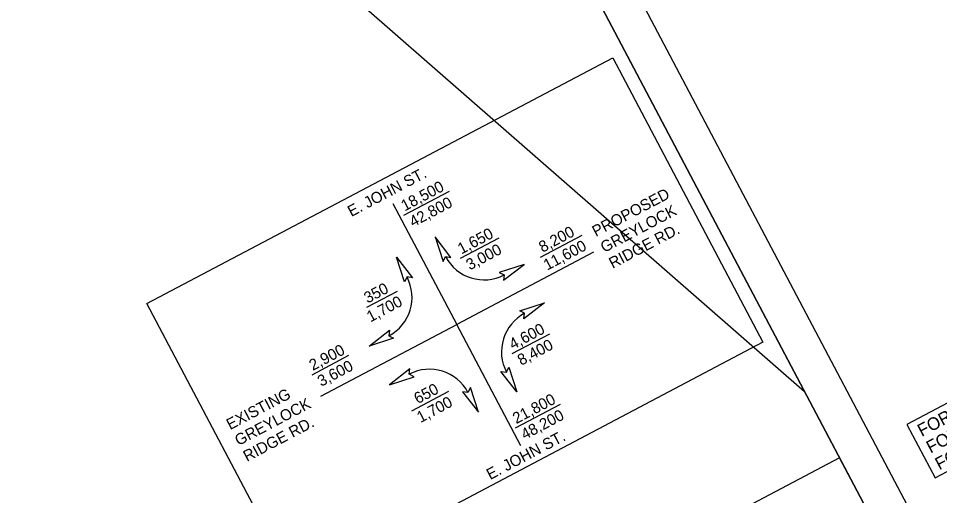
# Model space of a CAD drawing. Extents: x 1486990 to 1489232, y 497582 to 499336.
# Drawn here: x 1488614.3 to 1489025.8, y 498447.2 to 498660.3 of the extents above; entities that cross this region are included whole.
import ezdxf

# ---------------------------------------------------------------- set-up
doc = ezdxf.new("R2010")
doc.units = 0
for name, color, linetype in [('PROF-AXIS', 7, 'Continuous'), ('Prop Drainage Ditch Boundaries', 7, 'Continuous'), ('Prop Drainage Structure Catch Basin Open Throat 1 CELL', 7, 'Continuous'), ('Prop Drainage Structure Pipe Alternate 15in', 7, 'Continuous'), ('Prop Drainage Structure Plot Symbol 20 Scale', 7, 'Continuous'), ('Prop Earthen Structure V Ditch Berm Detail CELL', 7, 'Continuous')]:
    doc.layers.add(name, color=color, linetype=linetype)

msp = doc.modelspace()

# ---------------------------------------------------------------- linework, layer by layer
at = {"layer": 'PROF-AXIS'}
for p, q in [((1488786.47, 498572.43), (1488806.81, 498583.18)), ((1488781.55, 498577.59), (1488810.06, 498523.59)), ((1488811.79, 498553.19), (1488829, 498562.28)), ((1488847.53, 498553.72), (1488866.09, 498563.52)), ((1488871.18, 498555.86), (1488810.06, 498523.59)), ((1488769.91, 498531.28), (1488783.67, 498538.55)), ((1488749.37, 498491.54), (1488810.06, 498523.59)), ((1488838.69, 498469.38), (1488810.06, 498523.59)), ((1488834.76, 498510.59), (1488851.64, 498519.5)), ((1488745.45, 498501.2), (1488761.84, 498509.85)), ((1488789.93, 498485.11), (1488806.52, 498493.87)), ((1488836.33, 498477.44), (1488856.36, 498488.02))]:
    msp.add_line(p, q, dxfattribs=at)
for points in [[(1488807.43, 498553.6), (1488800.37, 498562.76), (1488803.93, 498551.68), (1488805.04, 498553.92)], [(1488786.76, 498542.69), (1488783.18, 498553.68), (1488790.32, 498544.5), (1488787.85, 498544.84)], [(1488831, 498543.42), (1488840.16, 498550.47), (1488829.08, 498546.91), (1488831.32, 498545.8)], [(1488838.25, 498529.69), (1488849.24, 498533.28), (1488840.05, 498526.14), (1488840.4, 498528.61)], [(1488781.88, 498517.48), (1488770.89, 498513.9), (1488780.07, 498521.03), (1488779.73, 498518.56)], [(1488789.13, 498503.75), (1488779.97, 498496.7), (1488791.05, 498500.26), (1488788.81, 498501.37)], [(1488833.37, 498504.48), (1488836.95, 498493.49), (1488829.81, 498502.67), (1488832.28, 498502.33)], [(1488812.7, 498493.57), (1488819.76, 498484.41), (1488816.2, 498495.49), (1488815.09, 498493.25)]]:
    msp.add_lwpolyline(points, close=True, dxfattribs=at)
for centre, start, end in [((1488822.24, 498563), 207.8351, 297.8351), ((1488770.65, 498535.76), 297.8351, 27.8351), ((1488849.48, 498511.41), 117.8351, 207.8351), ((1488797.89, 498484.17), 27.8351, 117.8351)]:
    msp.add_arc(centre, 19.44, start, end, dxfattribs=at)
at = {"layer": 'Prop Drainage Ditch Boundaries'}
msp.add_lwpolyline([(1487562.23, 497581.96), (1489050.94, 498368.04), (1488539.66, 499336.34), (1487050.94, 498550.27)], close=True, dxfattribs=at)
at = {"layer": 'Prop Drainage Structure Catch Basin Open Throat 1 CELL'}
for points in [[(1488535.14, 499308.53), (1487208.67, 498608.12), (1487698.94, 497679.61), (1489025.4, 498380.01)], [(1487698.94, 497679.61), (1487208.66, 498608.09), (1488358.21, 499215.12), (1488428.29, 499082.43), (1488605.19, 499175.82), (1489025.4, 498380.01)]]:
    msp.add_lwpolyline(points, close=True, dxfattribs=at)
at = {"layer": 'Prop Drainage Structure Plot Symbol 20 Scale'}
msp.add_lwpolyline([(1487208.67, 498608.09), (1488222.08, 499143.23), (1488965.38, 498493.69), (1489025.4, 498380.01), (1487698.95, 497679.62)], close=True, dxfattribs=at)
at = {"layer": 'Prop Earthen Structure V Ditch Berm Detail CELL'}
for points in [[(1488671.68, 498532.92), (1488879.76, 498642.79), (1488946.84, 498515.75), (1488738.76, 498405.88)], [(1489023.71, 498455.18), (1489232.03, 498565.18), (1489219.47, 498588.96), (1489011.16, 498478.96)], [(1488709.02, 498286.64), (1488994.97, 498437.63), (1488981.06, 498463.98), (1488695.11, 498312.99)]]:
    msp.add_lwpolyline(points, close=True, dxfattribs=at)

# ---------------------------------------------------------------- texts
at = {"layer": 'PROF-AXIS'}
for s, p in [('E. JOHN ST.', (1488762.96, 498571.58)), ('18,500', (1488786.81, 498574.08)), ('PROPOSED', (1488872.2, 498562.65)), ('42,800', (1488790.56, 498566.97)), ('GREYLOCK', (1488875.95, 498555.55)), ('1,650', (1488812.12, 498554.84)), ('8,200', (1488848.37, 498555.63)), ('RIDGE RD.', (1488879.7, 498548.44)), ('11,600', (1488850.46, 498547.64)), ('3,000', (1488815.87, 498547.73)), ('350', (1488770.24, 498532.93)), ('1,700', (1488771.49, 498524.5)), ('4,600', (1488835.09, 498512.23)), ('8,400', (1488838.85, 498505.13)), ('2,900', (1488745.78, 498502.84)), ('3,600', (1488749.53, 498495.73)), ('EXISTING', (1488708.83, 498476.39)), ('650', (1488792.62, 498487.99)), ('GREYLOCK', (1488712.58, 498469.29)), ('1,700', (1488793.87, 498479.56)), ('21,800', (1488836.66, 498479.08)), ('48,200', (1488840.41, 498471.98)), ('RIDGE RD.', (1488716.34, 498462.18)), ('E. JOHN ST.', (1488825, 498454.08))]:
    msp.add_text(s, height=5, rotation=27.8351, dxfattribs=at).set_placement(p)
at = {"layer": 'Prop Drainage Structure Pipe Alternate 15in'}
for s, p in [('FOR -SIDEPATH- ALIGNMENT DETAIL SEE SHEETS 2B-1 & 2B-2.', (1489021.7, 498465.9)), ('FOR -L- PROFILE SEE SHEET 6.', (1489017.76, 498473.36)), ('FOR -SIDEPATH- PROFILE SEE SHEET 8.', (1489025.64, 498458.43))]:
    msp.add_text(s, height=5.625, rotation=27.8351, dxfattribs=at).set_placement(p)

doc.saveas('drawing.dxf')
